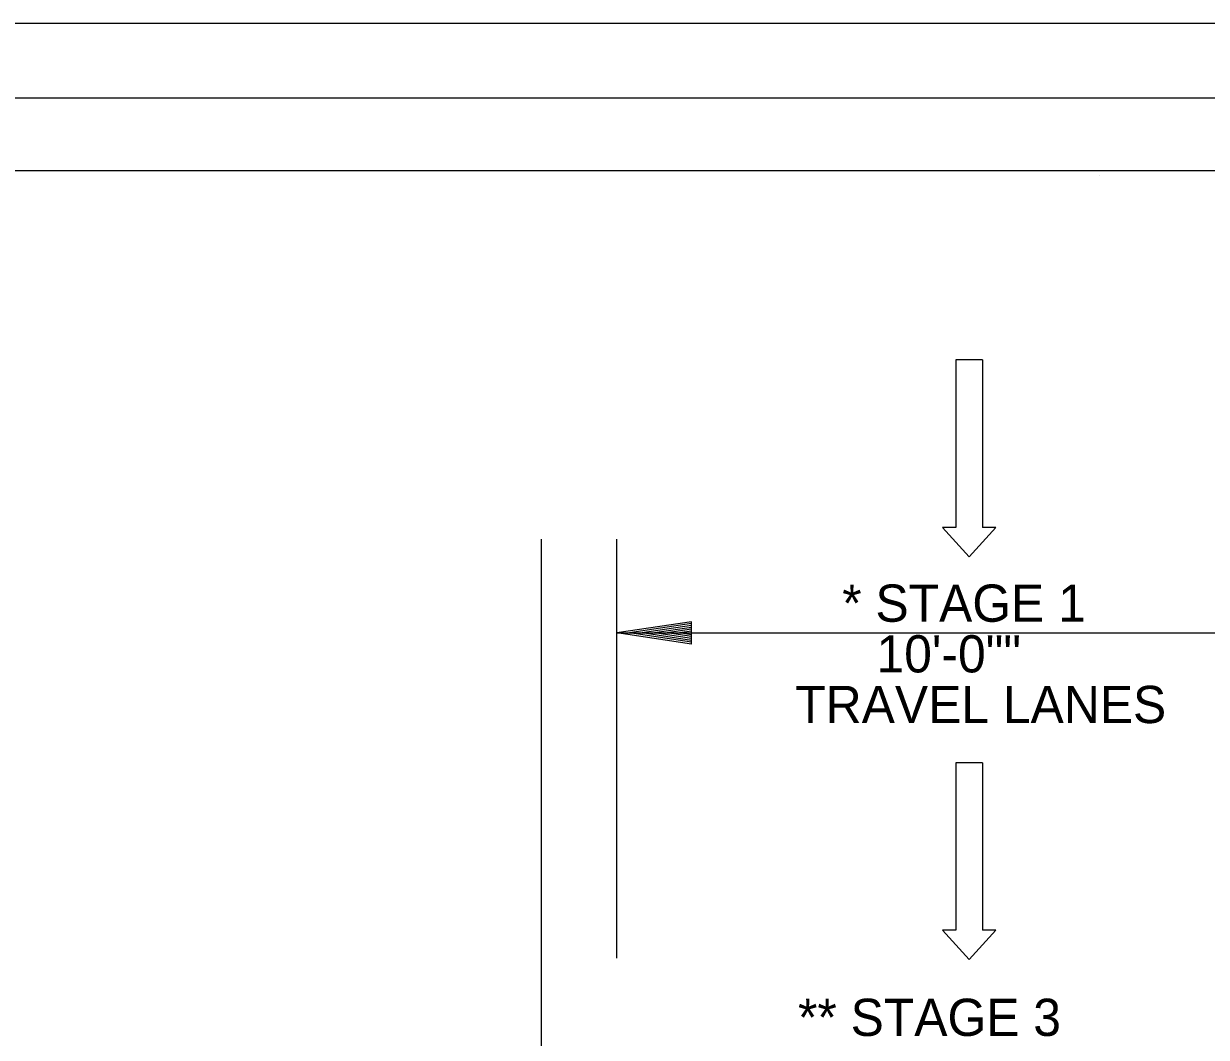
# Model space of a CAD drawing. Extents: x 6125 to 14104, y 8730 to 11067.
# Drawn here: x 8652.5 to 8970, y 10794.6 to 11066.7 of the extents above; entities that cross this region are included whole.
import ezdxf

# ---------------------------------------------------------------- set-up
doc = ezdxf.new("R2010")
doc.units = 0
for name, color, linetype in [('GREEN_TXT', 7, 'Continuous'), ('SEAL-INFO', 7, 'Continuous'), ('Stage 1 Construction', 7, 'Continuous')]:
    doc.layers.add(name, color=color, linetype=linetype)

msp = doc.modelspace()

# ---------------------------------------------------------------- linework, layer by layer
at = {"layer": 'GREEN_TXT'}
for p, q in [((9782.75, 11066.7), (8022.75, 11066.7)), ((8178.85, 11027.3), (9759.75, 11027.3)), ((8941.45, 11026), (8941.45, 11026)), ((8941.45, 11026), (8941.45, 11026))]:
    msp.add_line(p, q, dxfattribs=at)
at = {"layer": 'SEAL-INFO'}
msp.add_lwpolyline([(8116.81, 11046.77), (9783.51, 11046.77), (9783.51, 9980.09), (8116.81, 9980.09)], close=True, dxfattribs=at)
at = {"layer": 'Stage 1 Construction'}
for p, q in [((8909.95, 10976.43), (8909.95, 10931.47)), ((8791.5, 10637.08), (8791.5, 10928.28)), ((8811.77, 10815.82), (8811.77, 10928.28)), ((8831.77, 10906.15), (8811.77, 10903.15)), ((8831.77, 10905.65), (8815.11, 10903.15)), ((8831.77, 10905.14), (8818.55, 10903.15)), ((8831.77, 10904.64), (8821.88, 10903.15)), ((8831.77, 10900.15), (8831.77, 10906.15)), ((8811.77, 10903.15), (9005.34, 10903.15)), ((8831.77, 10900.15), (8811.77, 10903.15)), ((8831.77, 10900.65), (8815.11, 10903.15)), ((8831.77, 10901.16), (8818.55, 10903.15)), ((8831.77, 10901.66), (8821.88, 10903.15)), ((8831.77, 10904.13), (8825.27, 10903.15)), ((8831.77, 10902.18), (8825.27, 10903.15)), ((8831.77, 10903.62), (8828.61, 10903.15)), ((8831.77, 10902.68), (8828.61, 10903.15)), ((8909.95, 10868.33), (8909.95, 10823.37))]:
    msp.add_line(p, q, dxfattribs=at)
for points in [[(8909.95, 10976.43), (8902.75, 10976.43), (8902.75, 10931.47), (8899.15, 10931.47), (8906.35, 10923.58), (8913.55, 10931.47), (8909.95, 10931.47)], [(8909.95, 10868.33), (8902.75, 10868.33), (8902.75, 10823.37), (8899.15, 10823.37), (8906.35, 10815.47), (8913.55, 10823.37), (8909.95, 10823.37)]]:
    msp.add_lwpolyline(points, dxfattribs=at)

# ---------------------------------------------------------------- texts
for s, p in [('* STAGE 1', (8872.27, 10906.15)), ('10\'-0""', (8881.47, 10892.55)), ('TRAVEL LANES', (8859.67, 10878.95)), ('** STAGE 3', (8860.4, 10794.97))]:
    msp.add_text(s, height=10, dxfattribs=at).set_placement(p)

doc.saveas('drawing.dxf')
